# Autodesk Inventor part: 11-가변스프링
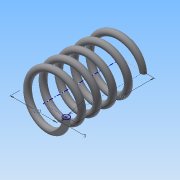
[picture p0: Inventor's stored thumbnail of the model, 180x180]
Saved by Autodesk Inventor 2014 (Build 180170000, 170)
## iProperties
Created: 2015-09
Part Number: 11-가변스프링
Material: 강철, 탄소
Document SubType Name: Modeling
Designer: study
Density: 7.87 g/cm^3
Appearance: 반연마
Mass: 18.6365 g
Surface Area: 32.4155 cm^2
Volume: 2.36804 cm^3
Author: study
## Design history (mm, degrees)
sketch "스케치1"
  geometry: L1 (0, 0)-(11, 0); L2 (11, 0)-(11, 25.208); L3 (11, 25.208)-(0, 25.208); L4 (0, 25.208)-(0, 0); C1 r 1.5 at (11, 0)
  constraints: 8 end point, 2 parallel, 1 centre point, 1 coincident, 1 horizontal, 1 perpendicular
  dimensions: "d0" = 3 diameter of C1; "d1" = 22 diameter of L1.end L4; "d2" = 25.20829 distance of L1.end L2.end (derived)
feature "코일1" sketch "스케치1" pitch "d3" = 10; turns "d5" = 5; dims "d4" = 25.20829 (= d2), "d6" = 0, angle "d7" = 90 deg, angle "d8" = 90 deg, "d9" = 0, "d10" = 0
node "작업 평면1"
sketch "스케치2"
  geometry: L1 (-12.5, 0)-(-9.5, 0) reference; 1 further point
  constraints: 1 horizontal alignment
extrude "돌출1" cut sketch "스케치2" stored distance "d12" = 10; taper "d13" = 0 deg
node "작업 평면2"
sketch "스케치3"
  geometry: L1 (-9.5, 0)-(-12.5, 0) reference; 1 further point
  constraints: 1 horizontal alignment
extrude "돌출2" cut sketch "스케치3" stored distance "d15" = 10; taper "d16" = 0 deg
node "솔리드1"
node "절단 모서리 투영1"
node "절단 모서리 투영2"
other parameters: "d11" = 0, "d14" = 25.20829 (= d2)
